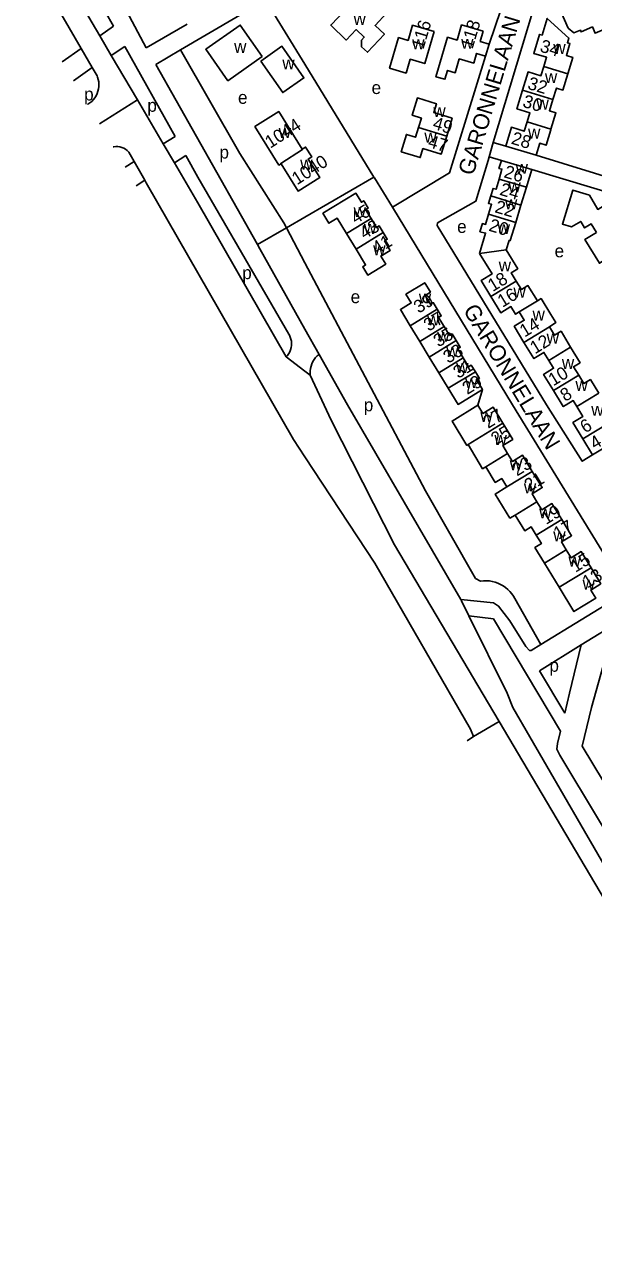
# Model space of a CAD drawing. Extents: x 157768 to 159790, y 387230 to 389604.
# Drawn here: x 157962.5 to 158140.1, y 388240.2 to 388618.6 of the extents above; entities that cross this region are included whole.
import ezdxf

# ---------------------------------------------------------------- set-up
doc = ezdxf.new("R2010")
doc.units = 0
for name, color, linetype in [('BLT_Basislijn', 7, 'Continuous'), ('BLT_Bebouwing', 7, 'Continuous'), ('BLT_Centroide', 7, 'Continuous'), ('BLT_Huisnummer', 7, 'Continuous'), ('BLT_Huisnummer_ tussenligend', 7, 'Continuous'), ('BLT_Onderverdeling_panden', 7, 'Continuous'), ('BLT_Straatnaam', 7, 'Continuous'), ('BLT_Vlakafsluiter', 7, 'Continuous')]:
    doc.layers.add(name, color=color, linetype=linetype)

msp = doc.modelspace()

# ---------------------------------------------------------------- linework, layer by layer
at = {"layer": 'BLT_Basislijn'}
for p, q in [((157962.48, 388655.01), (157986.06, 388614.92)), ((157968.1, 388657.61), (157990.31, 388617.94)), ((157962.48, 388641.6), (157980.2, 388611.06)), ((158037.75, 388626.22), (158011.18, 388610.56)), ((158050, 388606.19), (158037.75, 388626.22)), ((157986.06, 388614.92), (157990.31, 388617.94)), ((158013.32, 388618.59), (158000.54, 388611.19)), ((157986.06, 388614.92), (157989.62, 388608.86)), ((157974.33, 388606.88), (157980.2, 388611.06)), ((157980.2, 388611.06), (157983.65, 388605.1)), ((157989.62, 388608.86), (157993.83, 388611.67)), ((157993.83, 388611.67), (158009.53, 388583.62)), ((158011.18, 388610.56), (158003.52, 388606.04)), ((157989.62, 388608.86), (157997.78, 388594.98)), ((158035.23, 388549.92), (158003.52, 388606.04)), ((158071.54, 388570.98), (158050, 388606.19)), ((157977.86, 388600.97), (157983.65, 388605.1)), ((157983.65, 388605.1), (157985.18, 388602.47)), ((157997.78, 388594.98), (158005.8, 388581.35)), ((158005.8, 388581.35), (158009.53, 388583.62)), ((158005.8, 388581.35), (158009.31, 388575.38)), ((158107.5, 388577.29), (158108.72, 388581.71)), ((158108.72, 388581.71), (158112.61, 388580.64)), ((157993.92, 388574.08), (157996.7, 388575.84)), ((157995.05, 388578.73), (157996.7, 388575.84)), ((157996.7, 388575.84), (158000.07, 388569.95)), ((158009.31, 388575.38), (158012.86, 388577.67)), ((158009.31, 388575.38), (158016.64, 388562.93)), ((158012.86, 388577.67), (158016.64, 388570.93)), ((158111.31, 388576.16), (158107.5, 388577.29)), ((158156.23, 388567.27), (158122.1, 388577.76)), ((158120.74, 388573.29), (158155.25, 388562.98)), ((157997.39, 388568.26), (158000.07, 388569.95)), ((158000.07, 388569.95), (158000.54, 388569.12)), ((158044.97, 388522.05), (158016.64, 388570.93)), ((158050, 388558.49), (158071.54, 388570.98)), ((158071.69, 388570.73), (158071.54, 388570.98)), ((158071.69, 388570.73), (158077.31, 388561.59)), ((158016.64, 388562.93), (158044.11, 388514.91)), ((158043.46, 388556.66), (158044.25, 388555.15)), ((158044.25, 388555.15), (158050, 388558.49)), ((158035.23, 388549.92), (158044.25, 388555.15)), ((158044.25, 388555.15), (158050, 388544.28)), ((158035.95, 388548.64), (158035.23, 388549.92)), ((158050, 388523.61), (158035.95, 388548.64)), ((158054.42, 388515.73), (158050, 388523.61)), ((158071.81, 388450.63), (158050, 388483.75)), ((158136.14, 388425.22), (158203.35, 388466.31)), ((158103.15, 388445.92), (158104.77, 388445.1)), ((158115.48, 388439.69), (158123.53, 388425.32)), ((158123.53, 388425.32), (158150.45, 388441.73)), ((158113.11, 388410.16), (158101.13, 388434.22)), ((158123.17, 388417.14), (158136.14, 388425.22)), ((158136.14, 388425.22), (158132.52, 388410.19)), ((158123.17, 388417.14), (158131.05, 388403.96)), ((158132.52, 388410.19), (158131.05, 388403.96))]:
    msp.add_line(p, q, dxfattribs=at)
for points in [[(157969.4, 388667.99), (157989.17, 388632.57), (158000.54, 388611.19)], [(158111.05, 388623.11), (158107.47, 388612.37)], [(158108.72, 388581.71), (158121.28, 388623.33)], [(158043.46, 388556.66), (158029.7, 388578.31), (158011.18, 388610.56)], [(158106.36, 388608.66), (158095.07, 388572.26), (158077.31, 388561.59)], [(157982.25, 388593.62), (157982.31, 388593.66), (157982.93, 388594.07), (157983.51, 388594.55), (157984.03, 388595.08), (157984.49, 388595.67), (157984.89, 388596.3), (157985.21, 388596.98), (157985.46, 388597.68), (157985.64, 388598.41), (157985.74, 388599.15), (157985.75, 388599.9), (157985.69, 388600.64), (157985.55, 388601.38), (157985.33, 388602.09), (157985.18, 388602.47)], [(157990.17, 388580.36), (157990.43, 388580.42), (157991.06, 388580.49), (157991.69, 388580.47), (157992.31, 388580.38), (157992.92, 388580.21), (157993.5, 388579.96), (157994.04, 388579.64), (157994.54, 388579.25), (157995.05, 388578.73)], [(158139.7, 388484.4), (158136.49, 388482.42), (158125.36, 388500), (158091.21, 388555.89), (158091.37, 388556.68), (158103.25, 388563.43), (158107.17, 388576.11), (158107.5, 388577.29)], [(158050, 388483.75), (158046.43, 388489.18), (158000.54, 388569.12)], [(158150.45, 388441.73), (158114.7, 388500), (158077.31, 388561.59)], [(158050, 388544.28), (158087.58, 388473.17), (158103.15, 388445.92)], [(158044.11, 388514.91), (158044.56, 388515.41), (158044.96, 388515.95), (158045.29, 388516.54), (158045.54, 388517.17), (158045.72, 388517.82), (158045.83, 388518.48), (158045.85, 388519.16), (158045.79, 388519.83), (158045.66, 388520.49), (158045.44, 388521.13), (158045.16, 388521.74), (158044.97, 388522.05)], [(158054.42, 388515.73), (158053.84, 388515.25), (158053.33, 388514.71), (158052.87, 388514.12), (158052.48, 388513.48), (158052.15, 388512.8), (158051.91, 388512.09), (158051.74, 388511.36), (158051.64, 388510.62), (158051.63, 388509.87), (158051.68, 388509.29)], [(158098.59, 388439.32), (158063.24, 388500), (158054.42, 388515.73)], [(158077.94, 388456.36), (158058.16, 388495.23), (158051.68, 388509.29)], [(158110.53, 388401.36), (158077.94, 388456.36)], [(158071.81, 388450.63), (158101.61, 388398.93), (158102.6, 388396.67)], [(158104.77, 388445.1), (158105.68, 388445.19), (158106.6, 388445.19), (158107.52, 388445.12), (158108.42, 388444.97), (158109.31, 388444.74), (158110.17, 388444.43), (158111.01, 388444.05), (158111.8, 388443.6), (158112.56, 388443.08), (158113.27, 388442.5), (158113.92, 388441.86), (158114.51, 388441.16), (158115.05, 388440.41), (158115.48, 388439.69)], [(158101.13, 388434.22), (158098.84, 388438.88), (158098.59, 388439.32)], [(158098.59, 388439.32), (158108.77, 388438.28), (158110.4, 388437.31), (158113.87, 388432.66)], [(158178.76, 388441.33), (158143.06, 388418.7), (158139.38, 388405.72), (158136.41, 388393.63), (158179.39, 388322.58), (158180.5, 388321.56), (158181.92, 388320.82), (158191.87, 388317.6), (158193.81, 388323.44)], [(158101.13, 388434.22), (158108.77, 388433.3), (158129.69, 388398.29)], [(158113.87, 388432.66), (158118.88, 388424.71), (158120.06, 388423.49), (158120.54, 388423.49), (158123.53, 388425.32)], [(158113.11, 388410.16), (158114.86, 388405.67), (158151.9, 388341.7), (158159.71, 388328.7), (158186.97, 388280.59), (158201.92, 388257.55)], [(158208.36, 388240.19), (158188.03, 388270.59), (158110.53, 388401.36)], [(158129.69, 388398.29), (158128.76, 388394.44), (158128.6, 388392.76), (158129.54, 388390.8), (158165.68, 388330.67), (158174.35, 388317.04), (158187.03, 388312.04), (158186.97, 388310.6), (158183.77, 388300.45), (158202.51, 388268.96), (158206.29, 388262.91), (158207.24, 388262.31), (158216.68, 388260.1)], [(158102.6, 388396.67), (158100.57, 388395.31)]]:
    msp.add_lwpolyline(points, dxfattribs=at)
at = {"layer": 'BLT_Bebouwing'}
for p, q in [((158122.1, 388577.76), (158112.61, 388580.64)), ((158120.74, 388573.29), (158111.31, 388576.16)), ((158119.07, 388567.79), (158117.38, 388562.2)), ((158117.38, 388562.2), (158115.74, 388556.83)), ((158065.95, 388548.49), (158062.98, 388553.37)), ((158082.83, 388524.63), (158085.79, 388519.77)), ((158085.79, 388519.77), (158088.76, 388514.9)), ((158088.76, 388514.9), (158091.73, 388510.02)), ((158091.73, 388510.02), (158094.7, 388505.14)), ((158127.5, 388504.44), (158130.2, 388500)), ((158139.7, 388484.4), (158136.65, 388489.4)), ((158149.65, 388490.46), (158139.7, 388484.4)), ((158124.69, 388450.68), (158129.25, 388443.19))]:
    msp.add_line(p, q, dxfattribs=at)
for points in [[(158075.58, 388622.09), (158071.89, 388618.17), (158074.79, 388615.44), (158069.5, 388609.83), (158067.64, 388611.59), (158067.6, 388613.61), (158068.49, 388614.56), (158065.98, 388616.93), (158062.89, 388613.66), (158058.04, 388618.32), (158064.85, 388625.4), (158067, 388623.33), (158070.47, 388626.94), (158075.58, 388622.09)], [(158142.29, 388625.03), (158139.54, 388623.85), (158137.87, 388627.72), (158132.21, 388625.28), (158132.41, 388624.81), (158129.42, 388623.52), (158132.06, 388617.39), (158133.85, 388615.86), (158135.89, 388616.74), (158136.12, 388616.19), (158139.67, 388617.72), (158140.5, 388615.79), (158145.36, 388617.89)], [(158036.72, 388608.51), (158029.83, 388618.33), (158019.09, 388610.79), (158025.98, 388600.97), (158036.72, 388608.51)], [(158090.35, 388616.28), (158087.36, 388606.34), (158082.86, 388607.68), (158081.57, 388603.37), (158076.41, 388604.91), (158079.23, 388614.4), (158082.16, 388613.53), (158083.57, 388618.27), (158090.35, 388616.28)], [(158106.36, 388608.66), (158103.56, 388609.5), (158102.65, 388606.46), (158098.15, 388607.8), (158096.87, 388603.49), (158094.47, 388604.21), (158093.65, 388601.42), (158090.87, 388602.24), (158091.69, 388605.03), (158094.51, 388614.54), (158097.47, 388613.66), (158098.87, 388618.38), (158105.61, 388616.38)], [(158124.49, 388605.4), (158125.36, 388608.28), (158121.37, 388609.49), (158123.18, 388615.43), (158123.95, 388615.2), (158125.58, 388620.4), (158132.33, 388614.29), (158131.88, 388612.79), (158132.65, 388612.55), (158131.53, 388608.84), (158133.53, 388608.24), (158131.98, 388603.13)], [(158105.61, 388616.38), (158104.67, 388613.21), (158107.47, 388612.37)], [(158036.23, 388607.12), (158042.84, 388611.72), (158049.68, 388601.88), (158043.07, 388597.29), (158036.23, 388607.12)], [(158107.47, 388612.37), (158106.36, 388608.66)], [(158117.87, 388597.99), (158119.62, 388603.74), (158123.62, 388602.53), (158124.49, 388605.4)], [(158127.33, 388595.12), (158128.42, 388598.7), (158130.45, 388598.08), (158131.98, 388603.13)], [(158119.29, 388588.13), (158120.16, 388591.02), (158116.13, 388592.24), (158117.87, 388597.99)], [(158085.42, 388586.36), (158086.33, 388589.36), (158083.45, 388590.23), (158085.07, 388595.6), (158091.01, 388593.82), (158090.17, 388591.04), (158095.92, 388589.31), (158094.23, 388583.71)], [(158126.74, 388585.87), (158128.29, 388590.98), (158126.26, 388591.6), (158127.33, 388595.12)], [(158049.15, 388579.62), (158041.82, 388591.38), (158034.41, 388586.7), (158041.89, 388574.71), (158042.55, 388575.11)], [(158112.61, 388580.64), (158114.38, 388586.47), (158118.41, 388585.25), (158119.29, 388588.13)], [(158094.23, 388583.71), (158092.53, 388578.1), (158086.79, 388579.82), (158085.96, 388577.04), (158080.02, 388578.86), (158081.65, 388584.23), (158084.52, 388583.37), (158085.42, 388586.36)], [(158126.74, 388585.87), (158126.68, 388585.67), (158125.22, 388580.88), (158123.23, 388581.49), (158122.1, 388577.76)], [(158042.55, 388575.11), (158047.85, 388566.59), (158054.64, 388570.82), (158051.06, 388576.56), (158052.12, 388577.22), (158050.21, 388580.29), (158049.15, 388579.62)], [(158111.31, 388576.16), (158110.52, 388573.66), (158111.46, 388573.43), (158110.54, 388570.3)], [(158120.74, 388573.29), (158119.29, 388568.51), (158119.07, 388567.79)], [(158110.54, 388570.3), (158109.62, 388567.18), (158108.66, 388567.42), (158107.94, 388565.08)], [(158062.98, 388553.37), (158060.07, 388558.15), (158057.49, 388556.57), (158055.61, 388559.68), (158065.89, 388565.94), (158067.62, 388563.1), (158068.36, 388563.56), (158069.73, 388561.32), (158068.91, 388560.82), (158070.62, 388558.02)], [(158107.94, 388565.08), (158107.23, 388562.74), (158108.2, 388562.51), (158107.26, 388559.37)], [(158140.89, 388553.73), (158139.29, 388556.36), (158137.24, 388555.11), (158136, 388557.14), (158133.09, 388555.47), (158130.31, 388556.32), (158133.55, 388566.91), (158138.7, 388565.34), (158141.32, 388560.9), (158145.74, 388563.59), (158148.81, 388558.56)], [(158070.62, 388558.02), (158072.32, 388555.22), (158073.18, 388555.74), (158074.44, 388553.66)], [(158107.26, 388559.37), (158106.32, 388556.23), (158105.35, 388556.46), (158104.59, 388553.94), (158106.36, 388553.51), (158104.47, 388547.17)], [(158115.74, 388556.83), (158114.03, 388551.16), (158113.66, 388551.25), (158112.8, 388548.25)], [(158074.44, 388553.66), (158075.7, 388551.59), (158074.82, 388551.06), (158076.61, 388548.12), (158073.67, 388546.33), (158075.19, 388543.84), (158069.61, 388540.44), (158068.03, 388543.03), (158068.94, 388543.58), (158065.95, 388548.49)], [(158144.91, 388546.02), (158141.86, 388544.13), (158137.33, 388551.56), (158140.89, 388553.73)], [(158104.47, 388547.17), (158108.35, 388540.81), (158104.93, 388538.73), (158107.99, 388533.7)], [(158112.8, 388548.25), (158116.36, 388542.41), (158114.32, 388541.17), (158115.93, 388538.53)], [(158091.26, 388529.76), (158090, 388531.83), (158089.16, 388531.32), (158087.47, 388534.09), (158089.13, 388535.11), (158087.36, 388538.03), (158081.52, 388534.47), (158083.18, 388531.74), (158079.77, 388529.66), (158082.83, 388524.63)], [(158115.93, 388538.53), (158117.51, 388535.93), (158119.56, 388537.17), (158122.48, 388532.36)], [(158107.99, 388533.7), (158111.05, 388528.67), (158114.23, 388530.6), (158115.68, 388528.22), (158116.84, 388528.93)], [(158122.48, 388532.36), (158123.66, 388533.08), (158126.65, 388528.16), (158128.21, 388525.61), (158126.24, 388524.29)], [(158093.39, 388524.39), (158091.69, 388527.19), (158092.52, 388527.69), (158091.26, 388529.76)], [(158116.84, 388528.93), (158118.4, 388526.36), (158115.28, 388524.47), (158118.32, 388519.47)], [(158097.18, 388520.03), (158095.92, 388522.1), (158095.1, 388521.6), (158093.39, 388524.39)], [(158126.24, 388524.29), (158127.84, 388521.66), (158129.88, 388522.9), (158132.86, 388518.01)], [(158099.36, 388514.66), (158097.65, 388517.47), (158098.44, 388517.95), (158097.18, 388520.03)], [(158118.32, 388519.47), (158121.39, 388514.43), (158124.52, 388516.34), (158126.04, 388513.86)], [(158103.15, 388510.29), (158101.89, 388512.35), (158101.06, 388511.85), (158099.36, 388514.66)], [(158132.86, 388518.01), (158135.83, 388513.12), (158133.8, 388511.88), (158135.4, 388509.25)], [(158126.04, 388513.86), (158127.55, 388511.38), (158124.43, 388509.48), (158127.5, 388504.44)], [(158094.7, 388505.14), (158097.74, 388500.14), (158105.36, 388504.78), (158103.58, 388507.72), (158104.4, 388508.22), (158103.15, 388510.29)], [(158135.4, 388509.25), (158136.99, 388506.62), (158139.03, 388507.86), (158141.63, 388503.6)], [(158111.76, 388494.25), (158108.71, 388499.27), (158105.51, 388497.32), (158103.97, 388499.85), (158095.91, 388494.94), (158100.54, 388487.35), (158100.93, 388487.59)], [(158131.49, 388500), (158130.55, 388499.43), (158130.2, 388500)], [(158134.83, 388499.45), (158133.68, 388501.33), (158131.49, 388500)], [(158136.65, 388489.4), (158133.57, 388494.47), (158136.7, 388496.38), (158134.83, 388499.45)], [(158113.2, 388484.83), (158111.69, 388487.31), (158114.82, 388489.22), (158111.76, 388494.25)], [(158100.93, 388487.59), (158105.41, 388480.06), (158106.38, 388480.68)], [(158120.92, 388479.24), (158117.86, 388484.27), (158114.71, 388482.35), (158113.2, 388484.83)], [(158106.38, 388480.68), (158109.36, 388475.8), (158111.39, 388477.03), (158112.98, 388474.41)], [(158122.34, 388469.8), (158120.83, 388472.29), (158123.99, 388474.21), (158120.92, 388479.24)], [(158112.98, 388474.41), (158109.37, 388472.18), (158113.93, 388464.69), (158115.55, 388465.66)], [(158130.09, 388464.24), (158127.04, 388469.25), (158123.86, 388467.31), (158122.34, 388469.8)], [(158115.55, 388465.66), (158118.53, 388460.77), (158120.54, 388462), (158122.13, 388459.39)], [(158131.51, 388454.82), (158129.99, 388457.31), (158133.14, 388459.23), (158130.09, 388464.24)], [(158122.13, 388459.39), (158123.74, 388456.76), (158121.73, 388455.54), (158124.69, 388450.68)], [(158139.23, 388449.24), (158136.18, 388454.26), (158133.02, 388452.34), (158131.51, 388454.82)], [(158129.25, 388443.19), (158133.88, 388435.6), (158140.68, 388439.74), (158139.12, 388442.3), (158142.28, 388444.23), (158139.23, 388449.24)]]:
    msp.add_lwpolyline(points, dxfattribs=at)
at = {"layer": 'BLT_Onderverdeling_panden'}
for p, q in [((158124.49, 388605.4), (158131.98, 388603.13)), ((158117.87, 388597.99), (158127.33, 388595.12)), ((158119.29, 388588.13), (158126.74, 388585.87)), ((158085.42, 388586.36), (158094.23, 388583.71)), ((158110.54, 388570.3), (158119.07, 388567.79)), ((158107.94, 388565.08), (158117.38, 388562.2)), ((158070.62, 388558.02), (158062.98, 388553.37)), ((158107.26, 388559.37), (158115.74, 388556.83)), ((158074.44, 388553.66), (158065.95, 388548.49)), ((158104.47, 388547.17), (158112.8, 388548.25)), ((158107.99, 388533.7), (158115.93, 388538.53)), ((158116.84, 388528.93), (158122.48, 388532.36)), ((158091.26, 388529.76), (158082.83, 388524.63)), ((158093.39, 388524.39), (158085.79, 388519.77)), ((158126.24, 388524.29), (158118.32, 388519.47)), ((158097.18, 388520.03), (158088.76, 388514.9)), ((158099.36, 388514.66), (158091.73, 388510.02)), ((158132.86, 388518.01), (158126.04, 388513.86)), ((158103.15, 388510.29), (158094.7, 388505.14)), ((158135.4, 388509.25), (158127.5, 388504.44)), ((158141.63, 388503.6), (158134.83, 388499.45)), ((158100.93, 388487.59), (158111.76, 388494.25)), ((158144.56, 388494.21), (158136.65, 388489.4)), ((158113.2, 388484.83), (158106.38, 388480.68)), ((158112.98, 388474.41), (158120.92, 388479.24)), ((158122.34, 388469.8), (158115.55, 388465.66)), ((158130.09, 388464.24), (158122.13, 388459.39)), ((158131.51, 388454.82), (158124.69, 388450.68)), ((158139.23, 388449.24), (158129.25, 388443.19))]:
    msp.add_line(p, q, dxfattribs=at)
msp.add_lwpolyline([(158049.15, 388579.62), (158049.21, 388579.52), (158042.47, 388575.24), (158042.55, 388575.11)], dxfattribs=at)
at = {"layer": 'BLT_Vlakafsluiter'}
for p, q in [((157985.9, 388587.52), (157997.78, 388594.98)), ((158044.11, 388514.91), (158050, 388510.53)), ((158050, 388510.53), (158051.68, 388509.29)), ((158105.36, 388504.78), (158103.97, 388499.85))]:
    msp.add_line(p, q, dxfattribs=at)
msp.add_lwpolyline([(158102.6, 388396.67), (158110.53, 388401.36)], dxfattribs=at)

# ---------------------------------------------------------------- texts
at = {"layer": 'BLT_Centroide'}
for s, p in [('w', (158065.15, 388618.38)), ('w', (158083.44, 388610.81)), ('w', (158098.72, 388610.94)), ('w', (158027.91, 388609.66)), ('w', (158127.45, 388609.31)), ('w', (158042.95, 388604.52)), ('w', (158124.84, 388600.25)), ('p', (157981.14, 388594.82)), ('e', (158070.79, 388596.84)), ('p', (158000.86, 388591.3)), ('e', (158029.13, 388593.78)), ('w', (158122.2, 388591.97)), ('w', (158090.05, 388589.66)), ('w', (158041.81, 388583.17)), ('w', (158087.25, 388581.69)), ('w', (158119.58, 388582.94)), ('p', (158023.35, 388576.72)), ('w', (158048.52, 388573.31)), ('w', (158115.69, 388571.97)), ('w', (158113.45, 388566.25)), ('w', (158112.37, 388560.94)), ('w', (158065.17, 388558.47)), ('w', (158068.41, 388553.25)), ('e', (158097.46, 388553.56)), ('w', (158110.11, 388553.2)), ('w', (158071.28, 388546.61)), ('e', (158127.86, 388545.96)), ('p', (158030.44, 388539.17)), ('w', (158110.42, 388541.56)), ('e', (158064.27, 388531.68)), ('w', (158085.52, 388531.58)), ('w', (158115.03, 388533.38)), ('w', (158088.11, 388524.75)), ('w', (158120.97, 388526.27)), ('w', (158091.22, 388519.66)), ('w', (158125.38, 388519.06)), ('w', (158094.05, 388515.03)), ('w', (158097.16, 388509.91)), ('w', (158130.12, 388511.19)), ('w', (158099.95, 388505.22)), ('w', (158134.37, 388504.34)), ('p', (158068.35, 388497.99)), ('w', (158139.28, 388496.58)), ('w', (158104.7, 388494.62)), ('w', (158109.11, 388487.48)), ('w', (158113.86, 388479.62)), ('w', (158118.28, 388472.47)), ('w', (158123.04, 388464.59)), ('w', (158127.44, 388457.48)), ('w', (158132.17, 388449.62)), ('w', (158136.58, 388442.44)), ('p', (158126.24, 388416.84))]:
    msp.add_text(s, height=4, dxfattribs=at).set_placement(p)
at = {"layer": 'BLT_Huisnummer'}
for s, rotation, p in [('116', 73.2859, (158086.93, 388610.57)), ('118', 73.376, (158102.26, 388610.65)), ('34', 343.1157, (158123.02, 388610.13)), ('1044', 32.5915, (158039.17, 388579.76)), ('49', 343.2852, (158089.59, 388586.07)), ('47', 343.2852, (158088.11, 388580.37)), ('28', 343.1126, (158114.09, 388581.41)), ('1040', 32.5872, (158047.53, 388568.36)), ('26', 343.5545, (158111.8, 388570.94)), ('45', 31.3387, (158065.83, 388556.2)), ('20', 343.3299, (158107.09, 388554.29)), ('41', 31.3231, (158072.51, 388546.76)), ('39', 31.3361, (158085.46, 388528.35)), ('16', 31.3349, (158111.6, 388530.2)), ('33', 31.3361, (158094.67, 388512.75)), ('12', 31.3349, (158121.74, 388515.69)), ('29', 31.3361, (158100.63, 388503.06)), ('8', 31.3349, (158131.15, 388500.86)), ('27', 31.3399, (158107.13, 388492.48)), ('4', 31.3349, (158140.42, 388485.93)), ('21', 31.3399, (158119.96, 388472.82)), ('17', 31.3399, (158129.04, 388457.88)), ('13', 31.3399, (158138.08, 388442.73))]:
    msp.add_text(s, height=4, rotation=rotation, dxfattribs=at).set_placement(p)
at = {"layer": 'BLT_Huisnummer_ tussenligend'}
for s, rotation, p in [('32', 343.1126, (158119.17, 388598.51)), ('30', 343.1126, (158117.63, 388592.92)), ('24', 343.3299, (158110.47, 388565.48)), ('22', 343.3299, (158108.96, 388560.05)), ('43', 31.3231, (158068.56, 388551.44)), ('18', 31.3349, (158108.56, 388535.11)), ('37', 31.3361, (158088.56, 388522.74)), ('14', 31.3349, (158118.51, 388520.93)), ('35', 31.3361, (158091.62, 388517.83)), ('31', 31.3361, (158097.8, 388508.04)), ('10', 31.3349, (158127.45, 388505.71)), ('6', 31.3349, (158137.37, 388491.02)), ('25', 31.3399, (158109.55, 388487.3)), ('23', 31.3399, (158116.16, 388477.65)), ('19', 31.3399, (158125.2, 388462.55)), ('15', 31.3399, (158134.35, 388447.64))]:
    msp.add_text(s, height=4, rotation=rotation, dxfattribs=at).set_placement(p)
at = {"layer": 'BLT_Straatnaam'}
for rotation, p in [(73.2006, (158102.46, 388571.18)), (300.9495, (158099.21, 388529.5))]:
    msp.add_text('GARONNELAAN', height=5, rotation=rotation, dxfattribs=at).set_placement(p)

doc.saveas('drawing.dxf')
